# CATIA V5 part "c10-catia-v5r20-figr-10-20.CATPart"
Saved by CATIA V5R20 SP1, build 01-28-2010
Part number: Part1
Bounding box of the stored display mesh (mm): x -60 to 60, y -90 to 70, z -46.082 to 16.155
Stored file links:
  D:\v5_r20\psrt_files_downloaded\c10\c10-catia-v5r20-figr-10-20.CATPart
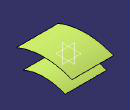
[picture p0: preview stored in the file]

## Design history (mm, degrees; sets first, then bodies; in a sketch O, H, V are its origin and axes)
Set1
  Sketch1 on yz-plane, origin (0, 0, 0), H (0, 1, 0), V (0, 0, 1)
    arc A1 centre (-10, -190) radius 206.1553 from (-90, 0) to (70, 0) cw
  Extrude1: Element1 Sketch1, Lim1 60, Lim2 60, Direction yz-plane
  Offset1: Offset Extrude1, Length 50
Body1 (main body)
